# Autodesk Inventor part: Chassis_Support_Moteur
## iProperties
Created: 2008-12
Part Number: Chassis_Support_Moteur
Document SubType Name: Sheet Metal
Designer: claivier
Author: claivier
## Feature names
1. Perçage1 [Hole]
2. Perçage2 [Hole]
3. Perçage3 [Hole]
4. Perçage4 [Hole]
5. Extrusion1
6. Miroir1 [Mirror]
7. Perçage5 [Hole]
8. Plaque1
9. Pli1
